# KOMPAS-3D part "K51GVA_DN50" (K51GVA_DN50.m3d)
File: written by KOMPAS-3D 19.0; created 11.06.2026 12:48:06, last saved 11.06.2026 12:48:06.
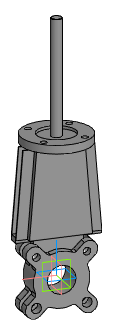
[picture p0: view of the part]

Document properties: Автор: Энергия; Полное имя файла: Z:\3.Личные\kachalov\001_3d для проектировщиков\2.6 Тип_K51GVA. Задвижка\_stp\_stp_K51GVA_DN50-DN1000_с фланцем\K51GVA_DN50.m3d

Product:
- Part/product: K51GVA_DN50

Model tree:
1. Операция без истории:1  (labels: K51GVA_DN50)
